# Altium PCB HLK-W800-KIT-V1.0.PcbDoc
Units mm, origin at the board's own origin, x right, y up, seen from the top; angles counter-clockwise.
Board outline 26.04 x 70.01 mm, 2 copper layers (Top Layer, Bottom Layer); 84 components, 58 nets, 293 pads, 279 vias.
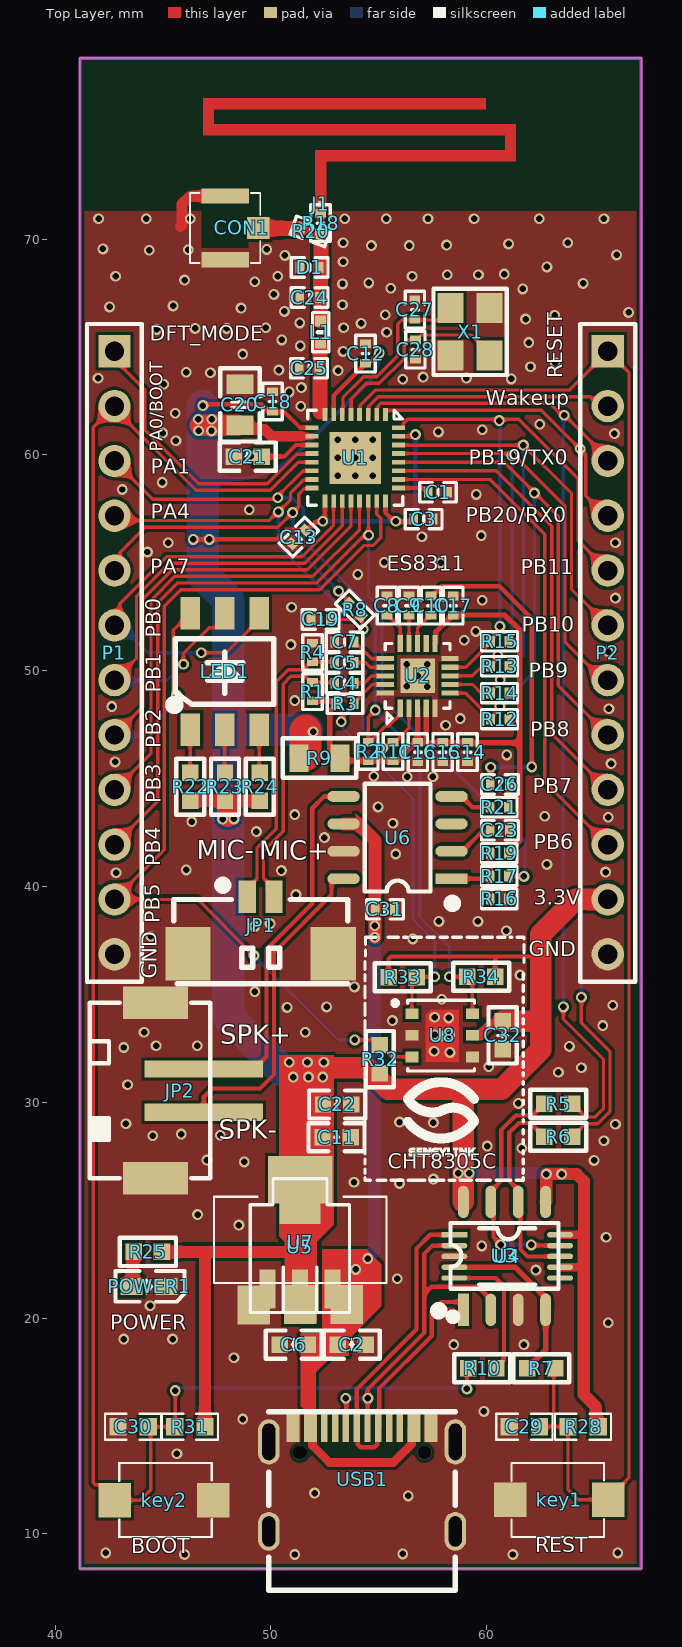
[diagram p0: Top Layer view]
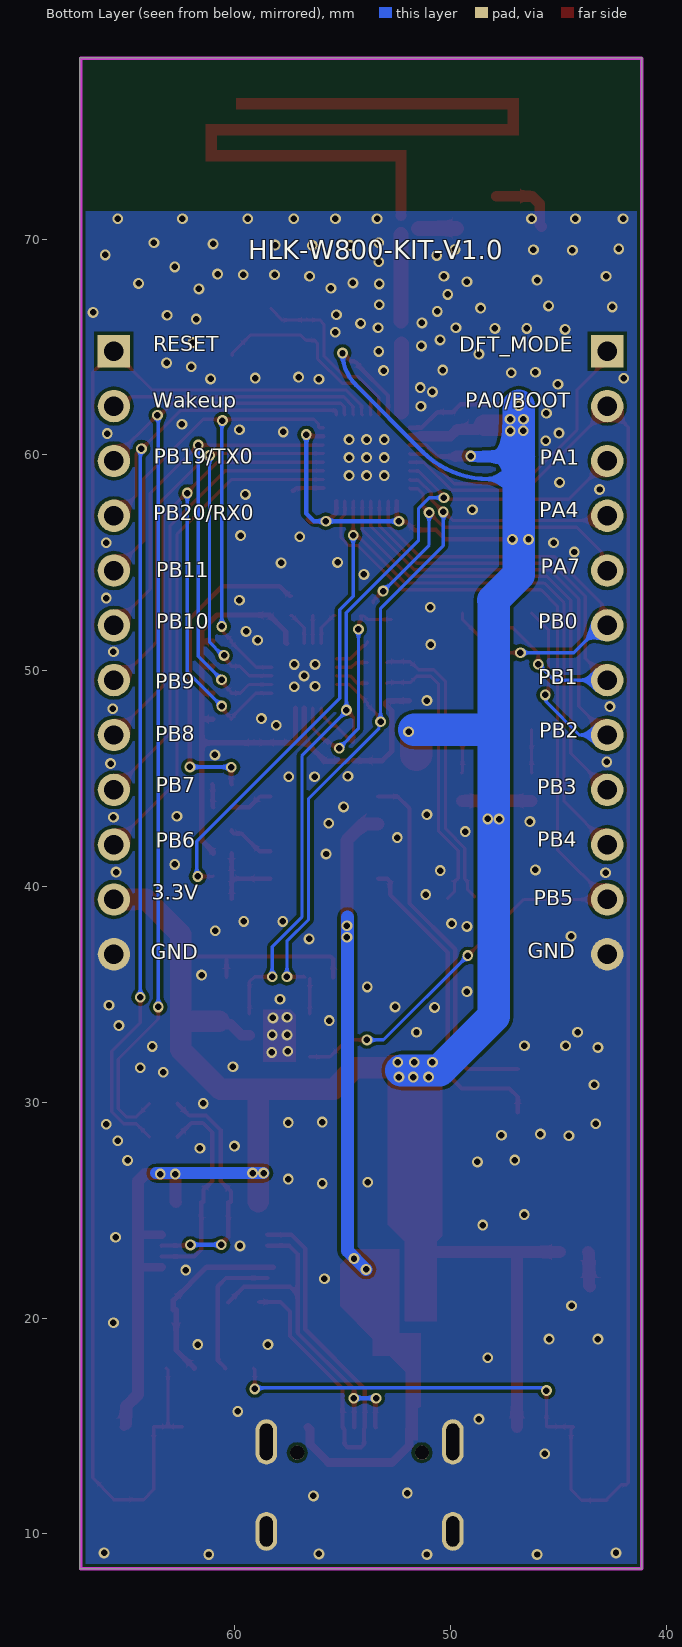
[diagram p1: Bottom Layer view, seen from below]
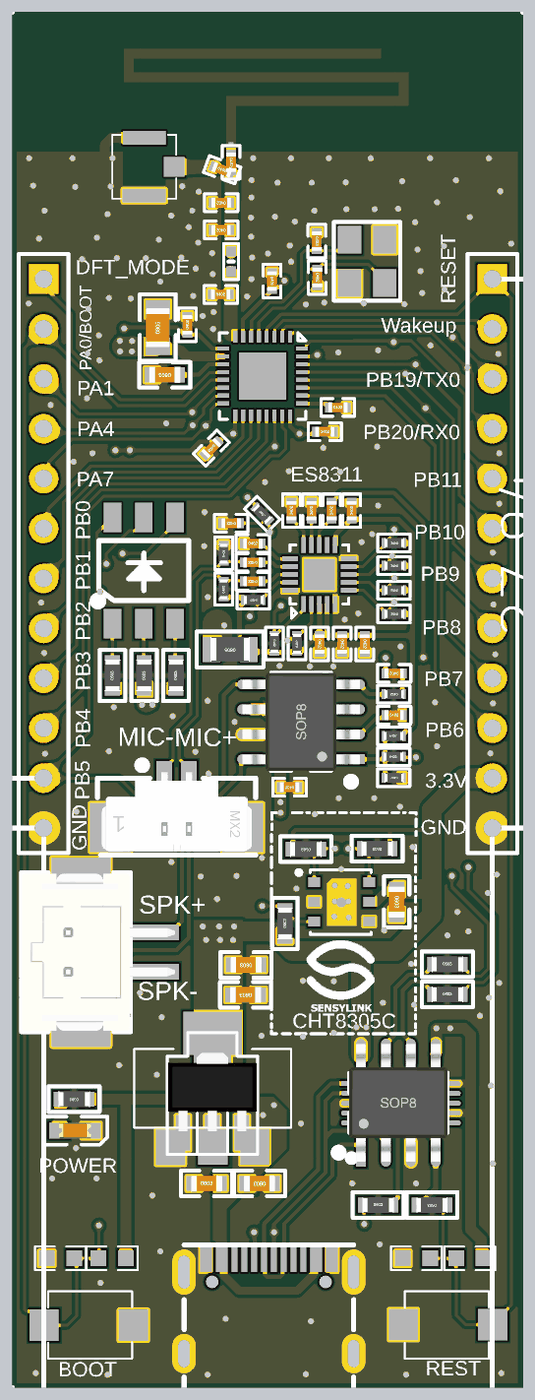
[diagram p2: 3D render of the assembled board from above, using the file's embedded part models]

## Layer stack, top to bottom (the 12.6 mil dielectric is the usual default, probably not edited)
Top Solder: solder mask 0.0102, Solder Resist, Dk 3.5
Top Layer: signal copper 0.0356
Dielectric1: dielectric 0.32, FR-4, Dk 4.8
Bottom Layer: signal copper 0.0356
Bottom Solder: solder mask 0.0102, Solder Resist, Dk 3.5

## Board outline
41.148,8.382 67.183,8.382 67.183,78.382 67.183,78.393 41.148,78.393 41.148,78.382

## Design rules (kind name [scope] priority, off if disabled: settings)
Clearance [All] p1: gap=0.152 ignorepadtopadclearanceinfootprint=FALSE except(0: Arc-Hole Track-Hole SMDPad-Hole THPad-Hole Via-Hole Fill-Hole Poly-Hole Region-Hole Text-Hole)
FabricationTestpoint [(IsPad And (OnTopLayer Or OnBottomLayer))] p1: side=3 testpointundercomponent=TRUE minsize=1.016 maxsize=2.54 preferedsize=1.524 minholesize=0 maxholesize=1.016 preferedholesize=0.813 testpointgrid=0.025 allowsidetop=TRUE allowsidebottom=TRUE usegrid=TRUE gridtolerance=0
PlaneConnect PlaneConnect_1 [InNet('5V')] p1: planeconnectstyle=Direct reliefexpansion=0.508 reliefentries=4 reliefconductorwidth=0.254 reliefairgap=0.254
PlaneConnect [All] p2: planeconnectstyle=Direct reliefexpansion=0.508 reliefentries=4 reliefconductorwidth=0.254 reliefairgap=0.254
PolygonConnect PolygonConnect_1 [InNet('5V')] p1: connectstyle=Direct reliefconductorwidth=0.254 reliefentries=4 polygonreliefangle="90 Angle" airgapwidth=0.254
PolygonConnect [All] p2: connectstyle=Direct reliefconductorwidth=0.254 reliefentries=4 polygonreliefangle="90 Angle" airgapwidth=0.254
RoutingVias [All] p1: holewidth=0.3 width=0.5 viastyle="Through Hole" minholewidth=0.3 minwidth=0.5 maxholewidth=0.5 maxwidth=0.7
SolderMaskExpansion [All] p1: expansion=0.1 istentingtop=FALSE
Width PWER [InNetClass('PWER')] p1: maxlimit=1 minlimit=0.18 preferedwidth=0.75
Width XINHAO [InNetClass('XINHAO')] p2: maxlimit=1 minlimit=0.254 preferedwidth=0.5
Width [All] p3: maxlimit=1.5 minlimit=0.152 preferedwidth=0.254
28 further rules are at their usual default settings.

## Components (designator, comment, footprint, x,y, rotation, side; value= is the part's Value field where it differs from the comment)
C1 "4.7uF" "C 0402_L" 57.742,58.266 r0 top
C2 "100nF" "C 0603_L" 53.746,18.771 r180 top
C3 "100nF" "C 0402_L" 57.074,57.023 r0 top
C4 "1uF" "C 0402_L" 53.409,49.42 r180 top
C5 "1uF" "C 0402_L" 53.409,50.377 r180 top
C6 "10UF" "C 0603_L" 51.054,18.771 r0 top
C7 "1uF" "C 0402_L" 53.409,51.333 r0 top
C8 "1uF" "C 0402_L" 55.372,53.01 r90 top
C9 "1uF" "C 0402_L" 56.396,53.01 r90 top
C10 "100nF" "C 0402_L" 57.421,53.01 r90 top
C11 "100nF" "C 0603_L" 53.037,28.374 r180 top
C12 "10nF" "C 0402_L" 54.381,64.694 r270 top
C13 "100nF" "C 0402_L" 51.292,56.19 r225 top
C14 "10uF" "C 0402_L" 59.106,46.226 r270 top
C15 "100nF" "C 0402_L" 57.956,46.226 r270 top
C16 "100nF" "C 0402_L" 56.806,46.226 r270 top
C17 "10uF" "C 0402_L" 58.445,53.01 r90 top
C18 "10nF" "C 0402_L" 50.072,62.471 r90 top
C19 "39pF" "C 0402_L" 52.306,52.375 r180 top
C20 "47uF" "C 0805_L" 48.565,62.321 r90 top
C21 "10uF" "C 0603_L" 48.92,59.921 r180 top
C22 "10UF" "C 0603_L" 53.061,29.896 r180 top
C23 "1uF" "C 0402_L" 60.604,42.606 r0 top
C24 "1pF" "C 0402_L" 51.791,67.29 r180 top
C25 "BDFN2C051L2" "C 0402_L" 51.765,64.011 r0 top
C26 "100nF" "C 0402_L" 60.604,44.729 r180 top
C27 "15pF" "C 0402_L" 56.667,66.729 r270 top
C28 "15pF" "C 0402_L" 56.693,64.874 r270 top
C29 "100nF" 0603 61.744,14.961 r180 top
C30 "100nF" 0603 43.608,14.961 r180 top
C31 "10uF" "C 0402_L" 55.278,38.938 r180 top
C32 "100nF" "C 0603_L" 60.731,33.096 r270 top value=100pF
CON1 "KH-IPEX-K501-29" SMA/UFLR/NI 47.879,70.513 r90 top
D1 "TPESD3301P" "C 0402_L" 51.795,68.683 r180 top
J1 "" TX1 52.297,71.635 r0 top
JP1 "HDR-1X2" "MX 1.25-LS-2P" 49.534,37.262 r0 top
JP2 "HDR-1X2" PH2.0-LS-2P 44.396,30.54 r90 top
key1 "按键" 正按小龟 65.63,11.586 r180 top
key2 "按键" 正按小龟 42.769,11.556 r0 top
L1 "3nH" 0402A 52.299,65.687 r90 top
LED1 "LED-RGB" "LED 5050" 47.854,49.962 r90 top
P1 "Header 12" HDR1X12 42.748,64.798 r270 top
P2 "Header 12" HDR1X12 65.608,64.798 r270 top
POWER1 "" LED0603 44.348,21.463 r0 top
R1 "2K" "R 0402_L" 51.92,49 r90 top
R2 "2.2K" "R 0402_L" 54.506,46.276 r270 top
R3 "2.2K" "R 0402_L" 53.459,48.463 r180 top
R4 "2K" "R 0402_L" 51.92,50.819 r90 top
R5 "0R" "R 0603_L" 63.315,29.93 r0 top
R6 "0R" "R 0603_L" 63.315,28.397 r0 top
R7 "1K" "R 0603_L" 62.531,17.679 r180 top
R8 "100" "R 0402_L" 53.87,52.851 r315 top
R9 "0R" "R 0805_L" 52.248,45.949 r180 top
R10 "1K" "R 0603_L" 59.792,17.678 r0 top
R11 "1K" "R 0402_L" 55.656,46.226 r90 top
R12 "1K" "R 0402_L" 60.624,47.752 r180 top
R13 "1K" "R 0402_L" 60.624,50.204 r180 top
R14 "1K" "R 0402_L" 60.624,48.96 r180 top
R15 "1K" "R 0402_L" 60.624,51.356 r180 top
R16 "10K" "R 0402_L" 60.604,39.421 r180 top
R17 "1K" "R 0402_L" 60.555,40.483 r0 top
R18 "0R" "C 0402_L" 52.299,70.739 r270 top
R19 "NC/1K" "R 0402_L" 60.555,41.544 r0 top
R20 "NC" "C 0402_L" 51.841,70.358 r340 top
R21 "15K" "R 0402_L" 60.604,43.668 r180 top
R22 "1K" "R 0603_L" 46.253,44.62 r90 top
R23 "1K" "R 0603_L" 47.869,44.62 r90 top
R24 "1K" "R 0603_L" 49.486,44.62 r90 top
R25 "4.7K" "R 0603_L" 44.298,23.063 r180 top
R28 "10K" 0603 64.462,14.961 r0 top
R31 "10K" 0603 46.239,14.961 r0 top
R32 "4.7K" "R 0603_L" 55.042,32.004 r90 top
R33 "4.7K" "R 0603_L" 56.109,35.789 r180 top
R34 "4.7K" "R 0603_L" 59.741,35.814 r180 top
U1 "W800" QFN32_4X4 53.905,59.861 r270 top
U2 "ES8311" ES8311 56.417,50.127 r270 top
U3 "CH340N" SOP8_L 60.822,22.881 r90 top
U4 "CH340E" MSOP10_L 60.949,22.856 r270 top
U5 "AMS1117-3V3" AMS1117 51.463,23.192 r180 top
U6 "ANT8108" SOP8_L 55.865,42.266 r180 top
U7 "AMS1117-3V3" SOT223 50.98,23.624 r90 top
U8 "CHT8305C" "DFN6 3X3" 57.785,33.071 r270 top
USB1 "USB_TYPE_C_16Pin" USB-C-16PIN-1 49.869,14.201 r0 top
X1 "40MHz/10ppm" SMD-3225 59.228,65.7 r90 top

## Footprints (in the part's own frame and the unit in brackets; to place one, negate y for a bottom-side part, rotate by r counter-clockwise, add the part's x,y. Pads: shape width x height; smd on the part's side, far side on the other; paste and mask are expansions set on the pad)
0402A [mil]
  rect 20x20 smd: 1(-20,0) 2(20,0)
  silkscreen extent -36,-15 36,15
0603 [mm]
  rect 0.8x0.8 smd: 1(-0.7,0) 2(0.7,0)
  silkscreen extent -1.3,-0.6 1.3,0.6
AMS1117 [mm] "4.6x4.3x1.6mm(长宽高)"
  rect 0.75x1.8 smd: 1(1.618,1.841) 2(0.118,1.841) 3(-1.382,1.841)
  rect 1.9x1.8 smd: 2(0.118,-2.059)
  silkscreen extent -2.18,-3.26 2.42,2.94, body extent -2.13,-2.23 2.37,1.77, height 1.5
"C 0402_L" [mm] "无极性贴片电容"
  rect 0.4x0.5 smd: 1(-0.45,0) 2(0.45,0)
  silkscreen extent -0.85,-0.45 0.85,0.45, body extent -0.5,-0.26 0.5,0.26, height 0.53
"C 0603_L" [mil] "无极性贴片电容"
  rect 30x30 smd: 1(-25.59,0) 2(25.59,0)
  silkscreen extent -51,-26 51,26, body extent -31,-16 31,16, height 32
"C 0805_L" [mil] "无极性贴片电容"
  rect 35x50 smd: 1(-37.4,0) 2(37.4,0)
  silkscreen extent -67,-36 67,36, body extent -39,-24 39,24, height 20
"DFN6 3X3" [mm]
  rect 0.5x0.6 smd: 1(-1.031,-1.254) 2(-0.031,-1.254) 3(0.969,-1.254) 4(-1.031,1.546) 5(-0.031,1.546) 6(0.969,1.546)
  round 0.5 smd mask+0.051: 7(0,0.127)
  Top Layer region: -1.211,0.913 1.19,0.913 1.19,-0.605 -0.975,-0.605 -1.211,-0.369
  silkscreen extent -1.65,-2.11 1.62,1.65
ES8311 [mm]
  rect 0.8x0.24 smd: 1(1.868,-0.422) 2(1.868,-0.022) 3(1.868,0.378) 4(1.868,0.778) 5(1.868,1.178) 11(-1.132,1.178) 12(-1.132,0.778) 13(-1.132,0.378) 14(-1.132,-0.022) 15(-1.132,-0.422)
  rect 0.24x0.8 smd: 6(1.168,1.878) 7(0.768,1.878) 8(0.368,1.878) 9(-0.032,1.878) 10(-0.432,1.878) 16(-0.432,-1.122) 17(-0.032,-1.122) 18(0.368,-1.122) 19(0.768,-1.122) 20(1.168,-1.122)
  rect 1.6x1.6 smd: 21(0.368,0.378)
  silkscreen extent -1.13,-1.12 2.58,1.88
HDR1X12 [mm] "Connector; Header; 12 Position"
  rect 1.5x1.5 hole 0.9: 1(0,0)
  round 1.5 hole 0.9: 2(2.54,0) 3(5.08,0) 4(7.62,0) 5(10.16,0) 6(12.7,0) 7(15.24,0) 8(17.78,0) 9(20.32,0) 10(22.86,0) 11(25.4,0) 12(27.94,0)
  silkscreen extent -1.27,-1.27 29.21,1.27
LED0603 [mm]
  rect 1x0.8 smd: 1(-0.81,0) 2(0.81,0)
  silkscreen extent -1.55,-0.71 1.65,0.71, body extent -0.81,-0.4 0.81,0.4, height 0.6
"LED 5050" [mm] "白色5050LED"
  rect 1.5x0.9 smd: 1(-2.705,1.6) 2(-2.705,0) 3(-2.705,-1.6) 4(2.705,-1.6) 5(2.705,0) 6(2.705,1.6)
  silkscreen extent -1.52,-2.29 1.52,2.29, body extent -2.7,-2.5 2.7,2.5, height 1.65
MSOP10_L [mm] "塑封体长3mm，宽3mm，脚距0.5"
  rect 0.25x1.2 smd: 1(-1,-2.45)
  oval 0.25x1.2 smd: 2(-0.5,-2.45) 3(0,-2.45) 4(0.5,-2.45) 5(1,-2.45) 6(1,2.45) 7(0.5,2.45) 8(0,2.45) 9(-0.5,2.45) 10(-1,2.45)
  silkscreen extent -1.3,-2.67 2.95,1.3, body extent -1.5,-2.45 1.5,2.45, height 0.95
"MX 1.25-LS-2P" [mm] "长：7.25m，宽：3.7mm，高：4.7mm"
  rect 2.1x2.5 smd: 0(-3.382,-0.381) 0(3.354,-0.381)
  rect 0.8x1.5 smd: 1(-0.639,2.261) 2(0.611,2.261)
  silkscreen extent -4.04,-1.78 4.02,2.99, body extent -3.83,-1.6 3.83,2.5, height 4.7
PH2.0-LS-2P [mm] "长：8mm，宽：5.5mm，高：6.1mm"
  rect 1.5x3 smd: 0(-4.064,-0.254) 0(4.064,-0.254)
  rect 0.8x5.5 smd: 1(-1,-2.492) 2(1,-2.492)
  silkscreen extent -4.06,-2.79 4.06,2.79, body extent -4,-5.05 4,2.75, height 6.15
QFN32_4X4 [mm]
  rect 0.6x0.22 smd: 1(-2,1.4) 2(-2,1) 3(-2,0.6) 4(-2,0.2) 5(-2,-0.2) 6(-2,-0.6) 7(-2,-1) 8(-2,-1.4) 17(2,-1.4) 18(2,-1) 19(2,-0.6) 20(2,-0.2) 21(2,0.2) 22(2,0.6) 23(2,1) 24(2,1.4)
  rect 0.22x0.6 smd: 9(-1.4,-2) 10(-1,-2) 11(-0.6,-2) 12(-0.2,-2) 13(0.2,-2) 14(0.6,-2) 15(1,-2) 16(1.4,-2) 25(1.4,2) 26(1,2) 27(0.6,2) 28(0.2,2) 29(-0.2,2) 30(-0.6,2) 31(-1,2) 32(-1.4,2)
  rect 2.4x2.4 smd: 33(0,0)
  silkscreen extent -2.2,-2.2 2.2,2.2
"R 0402_L" [mm] "1/16W贴片电阻"
  rect 0.4x0.5 smd: 1(-0.4,0) 2(0.45,0)
  silkscreen extent -0.8,-0.45 0.85,0.45, body extent -0.5,-0.25 0.5,0.25, height 0.3
"R 0603_L" [mil] "1/10W贴片电阻"
  rect 30x30 smd: 1(-25.59,0) 2(25.59,0)
  silkscreen extent -51,-26 51,26, body extent -31,-16 32,16, height 16
"R 0805_L" [mil] "1/8W贴片电阻"
  rect 35x50 smd: 1(-37.4,0) 2(37.4,0)
  silkscreen extent -67,-36 67,36, body extent -39,-25 39,25, height 20
SMA/UFLR/NI [mm] "一代天线座子"
  rect 1x1.05 smd: 1(0,-1.525)
  rect 0.7x2.2 smd: 2(-1.472,0.006) 3(1.475,0)
  Top Layer pour cut-out: -0.95,1.1 0.95,1.1 0.95,-1.1 0.5,-1.1 0.5,-1 -0.5,-1 -0.5,-1.1 -0.95,-1.1 -0.95,1.1
  silkscreen extent -1.63,-1.63 1.63,1.63
SMD-3225 [mm]
  rect 1.4x1.2 smd: 1(-1.1,-0.9) 2(1.1,-0.9) 3(1.1,0.9) 4(-1.1,0.9)
  silkscreen extent -2,-1.7 2,1.7
SOP8_L [mm] "5*6*1.8mm（长宽高）"
  rect 1.5x0.5 smd: 1(-2.5,1.905)
  oval 1.5x0.5 smd: 2(-2.5,0.635) 3(-2.5,-0.635) 4(-2.5,-1.905) 5(2.5,-1.905) 6(2.5,-0.635) 7(2.5,0.635) 8(2.5,1.905)
  silkscreen extent -2.69,-2.5 1.52,3.2, body extent -3,-2.5 3,2.5, height 1.9
SOT223 [mm] "6.4x7x1.6mm(长宽高)"
  rect 1.8x1.5 smd: 1(-3.017,1.772) 2(-2.995,-0.384) 3(-2.995,-2.534)
  rect 2.2x3 smd: 2(2.794,-0.381)
  silkscreen extent -2.01,-4.38 1.99,3.62
TX1 [mil]
  rect 10x10 smd mask+3.94: 1(0,0)
  Top Layer region: 301.34,192.19 -214.41,192.19 -214.41,125.26 336.77,125.26 336.77,97.7 -9.68,97.7 -9.68,-15 10,-15 10,78.02 356.46,78.02 356.46,144.94 -194.72,144.94 -194.72,172.5 301.34,172.5
USB-C-16PIN-1 [mm]
  oval 1x2.099 hole 0.6 slot 1.7 at 90 deg: 1(0.034,0.061) 2(8.674,0.061)
  oval 1x1.799 hole 0.6 slot 1.4 at 90 deg: 3(0.034,-4.088) 4(8.674,-4.088)
  rect 0.6x1.35 smd: A1B12(1.154,0.736) A4B9(1.954,0.736) B1A12(7.554,0.736) B4A9(6.754,0.736)
  rect 0.3x1.35 smd: A5(3.104,0.736) A6(4.104,0.736) A7(4.604,0.736) A8(2.604,0.736) B5(6.104,0.736) B6(5.104,0.736) B7(3.604,0.736) B8(5.604,0.736)
  round 0.65 hole 0.65 unplated: ""(1.464,-0.438) ""(7.244,-0.438)
  silkscreen extent 0.04,-6.81 8.67,1.45
正按小龟 [mm]
  rect 1.5x1.6 smd: 1(0,0) 2(4.55,0)
  silkscreen extent 0.2,-1.7 4.48,1.73

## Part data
C1 C3 C4 C5 C7 C8 C9 C10 C12 C13 C14 C15 C16 C17 C18 C19 C20 C21 C23 C24 C26 C31 R18 R20: library part "CAP NP_Dup2"
C2 C6 C11 C22: library part C, "无极性贴片电容"
C25: library part "CAP NP"
C27 C28 C29 C30: library part "CAP NP_Dup1"
C32: library part Cap, "Capacitor"
CON1: BOM_Manufacturer="Shenzhen Kinghelm Elec"
D1: library part PT05D5CE, BOM_Manufacturer="PTTC(Polytronics Tech)"
J1: library part Component_1
JP1 JP2: library part "Header 2", "2P接插件"
L1: library part INDUCTOR
LED1: "三基色LED"
P1 P2: "Header, 12-Pin"
POWER1: library part LED
R1 R4: library part R_Dup1
R2 R3 R9 R16 R21: library part RES
R5 R6 R7 R10 R22 R23 R24 R25 R28 R31 R32 R33 R34: library part Res1, "Resistor"
R8: library part RES1, "R?"
R11 R12 R13 R14 R15 R17 R19: library part R
U1: library part W600_10
U2: library part ES8374_0
U3: BOM_JLCPCB Part Class="Extended Part", BOM_Manufacturer="WCH(Jiangsu Qin Heng)"
U5 U7: library part AMS1117, "三端稳压芯片"
U6: library part W25Q16_5
U8: "温度传感器"
X1: library part OSC44M_5

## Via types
v1: diameter 0.5, hole 0.3, Top Layer to Bottom Layer, tented both sides, 279 vias

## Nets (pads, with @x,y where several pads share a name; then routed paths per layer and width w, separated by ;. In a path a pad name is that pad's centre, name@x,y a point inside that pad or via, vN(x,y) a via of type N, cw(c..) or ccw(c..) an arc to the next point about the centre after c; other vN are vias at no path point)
5V: C2.2 C6.2 C31.2 U5.3 U6.6 U7.3 USB1.A4B9 USB1.B4A9 | length 29.9
  Top Layer w0.4: USB1.A4B9 51.923,14.838 51.923,14.096 52.714,13.305 55.665,13.305 56.523,14.164 56.523,14.838 USB1.B4A9
  Top Layer w0.6: U6.6 54.051,42.901 54.813,42.139 v1(54.813,38.176) v1(54.813,37.643)
  Bottom Layer w0.6: v1(53.924,22.25) 54.788,23.114 54.788,38.583
  other v1: 54.483,22.758
ANT: C25.2 L1.1 U1.8 | length 3.2
  Top Layer w0.7: C25.2@52.273,64.011 L1.1@52.273,65.128 ; 52.277,61.979 C25.2@52.277,64.04
CH_DM: U3.2 U4.2 USB1.A7 USB1.B7 | length 16.7
  Top Layer w0.2: v1(53.463,16.286) 53.493,16.256 53.493,14.957 USB1.B7 ; USB1.A7 54.473,16.286 54.473,16.688 57.097,19.312 57.097,21.101 ; U4.2 57.489,23.356 57.097,22.964 57.097,21.101 ; U3.2@60.314,20.719 59.583,21.45 57.446,21.45 57.097,21.101
  Bottom Layer w0.2: v1(53.463,16.286) v1(54.493,16.286) v1@54.498,16.281
CH_DP: U3.1 U4.1 USB1.A6 USB1.B6 | length 22.1
  Top Layer w0.2: USB1.B6 55.013,14.977 55.013,16.729 57.449,19.166 57.449,20.303 57.894,20.748 U3.1@58.872,20.748 ; USB1.B6@54.998,14.913 54.923,14.838 54.923,14.144 54.79,14.01 54.157,14.01 54.023,14.144 54.023,14.888 USB1.A6 53.981,14.945 53.981,16.715 56.745,19.479 56.745,23.222 57.379,23.856 U4.1
DAC_OUT: C10.2 C26.2 | length 15.1
  Top Layer w0.2: C10.2 57.471,53.46 57.923,53.912 60.593,53.912 62.088,52.417 v1(62.088,45.537) ; C26.2 60.142,44.742 60.176,44.777 60.176,45.52 v1(60.174,45.522)
  Bottom Layer w0.2: v1(60.174,45.522) 60.188,45.537 v1(62.088,45.537)
DFT_MODE: P1.1 U1.12 | length 13.6
  Top Layer w0.152: P1.1@42.494,64.672 44.145,63.021 44.145,61.172 46.652,58.665 49.836,58.665 51.205,60.034 51.675,60.034 51.878,60.034 U1.12
GND: C1.2 C2.1 C3.2 C6.1 C7.1 C8.2 C9.2 C11.1 C12.1 C13.2 C14.2 C15.2 C16.2 C17.2 C18.2 C19.2 C20.2 C21.2 C22.1 C23.2 C24.2 C25.1 C27.1 C28.2 C29.2 C30.2 C31.1 C32.2 CON1.2 CON1.3 D1.2 JP1.0 JP2.0 key1.2 key2.2 P1.12 P2.12 POWER1.2 R4.2 R16.1 U1.33 U2.5 U2.10 U2.20 U2.21 U3.3 U4.3 U5.1 U6.7 U7.1 U8.2 U8.6 U8.7 USB1.1 USB1.2 USB1.3 USB1.4 USB1.A1B12 USB1.B1A12 X1.2 X1.4 | length 3.2
  Top Layer w0.5: 45.796,70.587 45.872,70.663 45.872,71.628 46.233,71.988 CON1.3
  other v1: 45.999,9.042 51.105,9.042 61.214,9.042 56.109,9.068 42.342,9.119 66.065,9.119 56.363,11.76 52.019,11.887 45.644,13.716 48.692,15.316 59.868,15.672 48.285,18.161 58.471,18.771 61.722,18.771 43.18,19.025 45.441,19.025 65.634,19.787 44.399,20.574 55.855,21.819 62.281,22.225 59.766,23.343 65.532,23.749 48.514,24.308 46.598,24.792 55.956,26.238 53.848,26.289 57.531,26.441 48.763,27.237 47.034,27.317 64.973,27.305 61.62,27.864 60.025,27.971 65.43,28.219 44.526,28.448 47.65,28.473 45.847,28.524 65.962,28.981 43.282,29.007 57.531,29.058 55.956,29.083 61.468,29.947 43.358,30.81 63.322,31.394 64.389,31.598 60.096,31.648 58.293,32.309 57.556,32.36 43.18,32.537 63.83,32.588 44.679,32.614 46.584,32.614 57.582,33.122 58.268,33.122 44.12,33.249 51.587,33.249 65.38,33.553 55.626,33.782 58.242,33.909 57.582,33.934 50.749,34.392 52.578,34.417 65.837,34.493 57.912,34.773 49.251,35.128 53.869,35.342 61.544,35.89 56.566,37.567 44.425,37.694 60.909,37.948 49.251,38.151 49.962,38.278 57.785,38.379 59.588,38.379 51.156,39.624 42.824,40.64 65.507,40.665 50.486,40.739 46.076,40.767 62.789,41.021 55.778,41.504 52.476,42.266 49.327,42.545 55.651,42.926 46.331,43.007 65.634,43.205 62.687,43.256 51.105,43.332 54.966,43.688 56.312,45.085 57.506,45.085 54.762,45.11 65.761,45.695 42.774,45.771 60.928,46.095 58.09,47.473 58.776,47.777 65.659,48.235 42.621,48.336 51.105,48.616 57.252,49.251 56.286,49.276 56.794,49.759 56.286,50.292 57.252,50.292 65.634,50.876 50.927,51.206 58.953,51.41 59.487,51.816 50.952,52.934 59.792,53.264 65.964,53.365 54.026,54.458 57.861,54.991 55.245,55.016 44.272,55.499 45.237,55.931 65.964,55.931 56.998,56.21 59.741,56.261 48.995,57.452 59.512,58.166 43.104,58.395 44.958,58.725 53.086,59.042 53.899,59.042 54.712,59.042 53.086,59.875 53.899,59.875 54.712,59.875 45.593,60.655 53.086,60.709 53.899,60.709 54.712,60.709 65.913,60.985 44.983,61.011 57.76,61.062 59.792,61.166 62.459,61.417 45.568,61.925 51.384,62.255 50.851,62.916 51.41,63.119 45.034,63.271 56.109,63.5 61.13,63.52 41.986,63.551 59.056,63.557 57.048,63.602 47.193,63.805 46.076,63.83 53.111,63.906 50.368,63.932 62.027,64.084 63.17,64.262 48.692,64.668 53.34,64.795 51.359,65.049 61.951,65.202 50.495,65.329 55.356,65.679 44.704,65.811 46.482,65.862 47.955,65.862 49.759,65.888 53.365,65.888 54.178,66.091 51.333,66.116 61.798,66.294 63.144,66.472 55.296,66.497 66.573,66.599 50.622,66.65 48.616,66.802 42.52,66.853 45.466,66.904 53.315,66.954 50.14,67.437 61.671,67.691 55.55,67.716 53.315,67.92 64.465,67.945 54.534,67.97 49.251,68.021 45.999,68.097 42.799,68.275 50.317,68.275 56.54,68.275 58.166,68.351 59.614,68.351 60.808,68.377 62.789,68.707 53.34,68.947 50.648,69.243 66.015,69.266 44.361,69.483 46.169,69.505 49.809,69.52 42.215,69.545 54.658,69.7 56.409,69.7 58.141,69.723 61.011,69.774 53.34,69.832 63.754,69.825 42.012,70.942 44.221,70.942 46.256,70.942 53.416,70.942 55.347,70.942 57.277,70.942 59.411,70.942 62.433,70.942 65.43,70.942
MIC+: C4.2 JP1.2 R1.2 | length 13.2
  Top Layer w0.152: JP1.2@50.145,39.446 49.821,39.77 49.821,40.221 49.656,40.387 49.656,41.652 50.565,42.56 50.565,49.379 50.923,49.737 51.584,49.737 51.87,49.45 52.929,49.45 C4.2
MIC-: C5.2 JP1.1 R4.1 | length 13.6
  Top Layer w0.152: JP1.1 49.219,39.846 49.219,40.218 49.351,40.35 49.351,41.778 50.24,42.666 50.24,49.485 50.796,50.042 51.493,50.042 51.87,50.419 R4.1 52.917,50.419 C5.2
NetC1_1: C1.1 U1.25 | length 1.5
  Top Layer w0.2: U1.25 57.156,58.461 57.278,58.339 C1.1@57.328,58.339
NetC4_1: C4.1 U2.18 | length 1.6
  Top Layer w0.152: C4.1 54.329,49.42 54.666,49.756 55.292,49.756 U2.18
NetC5_1: C5.1 U2.17 | length 1.5
  Top Layer w0.152: C5.1 54.39,50.377 54.608,50.159 U2.17
NetC7_2: C7.2 U2.16 | length 1.8
  Top Layer w0.152: C7.2 53.859,51.283 53.983,51.16 54.065,51.16 54.666,50.559 U2.16
NetC8_1: C8.1 U2.15 | length 1.6
  Top Layer w0.152: C8.1 55.422,52.56 55.994,51.987 U2.15
NetC9_1: C9.1 U2.14 | length 1.3
  Top Layer w0.152: U2.14 56.394,52.558 C9.1
NetC10_1: C10.1 U2.13 | length 1.6
  Top Layer w0.152: U2.13 56.794,51.983 57.371,52.56 C10.1
NetC23_1: C23.1 U6.2 | length 2.2
  Top Layer w0.2: U6.2 58.865,41.631 59.691,42.456 60.054,42.456 60.154,42.556 C23.1
NetC24_1: C24.1 D1.1 L1.2 R18.2 R20.2 | length 4
  Top Layer w0.7: L1.2 52.299,67.313 D1.1@52.299,68.766 ; D1.1@52.313,68.806 R20.2@52.313,70.209
NetC26_1: C26.1 R21.1 | length 1.1
  Top Layer w0.2: R21.1 61.029,43.693 61.029,44.704 C26.1
NetCON1_1: CON1.1 R20.1 | length 1.8
  Top Layer w0.7: CON1.1@49.727,70.494 R20.1@51.486,70.494
NetJ1_1: J1.1 R18.1 | length 0
  Top Layer w0.5: R18.1@52.299,71.082 52.299,71.106 R18.1@52.302,71.11
NetLED1_1: LED1.1 R22.2 | length 2
  Top Layer w0.152: R22.2 LED1.1
NetLED1_2: LED1.2 R23.2 | length 2
  Top Layer w0.152: LED1.2 47.854,45.285 R23.2
NetLED1_3: LED1.3 R24.2 | length 2
  Top Layer w0.152: LED1.3 49.454,45.302 R24.2
NetPOWER1_1: POWER1.1 R25.2 | length 1.6
  Top Layer w0.56: POWER1.1 43.593,21.518 43.593,23.009 R25.2
NetR10_2: R10.2 U4.5 | length 6.4
  Top Layer w0.2: U4.5 60.415,21.856 60.8,21.47 60.8,18.037 R10.2
NetR16_2: R16.2 R17.1 R19.1 U6.1 | length 4
  Top Layer w0.2: U6.1 60.054,40.361 R17.1@60.154,40.461 ; R16.2 R17.1@60.154,40.461 ; R19.1 R17.1 R17.1@60.154,40.461
NetR21_2: R21.2 U6.4 | length 2
  Top Layer w0.2: U6.4 58.835,44.171 59.338,43.668 R21.2
PA0/BOOT: C30.1 key2.1 P1.2 R10.1 R31.1 U1.13 | length 85.4
  Top Layer w0.152: v1(45.568,16.637) 45.568,14.99 R31.1 C30.1 44.425,14.845 44.425,12.04 43.941,11.556 key2.1 42.769,11.606 42.095,12.28 41.859,12.28 41.77,12.369 41.77,61.28 P1.2 42.748,62.138 46.526,58.36 49.962,58.36 51.263,59.661 51.326,59.661 U1.13 ; v1(59.08,16.713) 59.08,17.617 R10.1
  Bottom Layer w0.152: v1(45.568,16.637) 45.662,16.637 45.789,16.765 59.029,16.765 v1(59.08,16.713)
PA1: P1.3 R2.1 R34.2 U1.14 U2.1 U8.4 | length 43
  Top Layer w0.152: P1.3 44.529,57.937 50.054,57.937 50.064,57.947 50.251,57.947 v1(50.317,58.014) 50.317,58.093 51.472,59.248 51.892,59.248 51.895,59.251 U1.14 ; v1(54.837,48.172) 54.506,47.841 R2.1 54.556,46.676 55.33,47.449 55.465,47.449 55.994,47.979 U2.1 ; v1(58.268,35.814) R34.2 59.331,35.574 U8.4
  Bottom Layer w0.152: v1(50.317,58.014) 50.994,58.014 51.489,57.518 51.489,56.039 54.837,52.692 v1(54.837,48.172) 54.837,48.11 56.896,46.05 56.896,38.583 58.276,37.202 v1@58.276,35.814 ; v1(58.268,35.814) v1@58.276,35.814
PA4: P1.4 R3.1 R33.1 U1.15 U2.19 U8.1 | length 40.2
  Top Layer w0.152: P1.4 42.967,56.959 49.916,56.959 50.31,57.353 v1(50.343,57.353) 50.343,57.362 50.907,57.927 50.907,58.235 51.5,58.827 51.872,58.827 U1.15 ; v1(53.254,47.634) 53.321,47.701 53.321,47.875 53.859,48.413 R3.1 53.859,48.513 54.704,49.359 U2.19 ; U8.1 56.531,35.728 R33.1@56.54,35.738 ; R33.1 56.809,35.839 56.835,35.814 v1(57.591,35.814)
  Bottom Layer w0.152: v1(50.343,57.353) 50.343,55.795 53.254,52.884 v1(53.254,47.634) 53.321,47.568 53.321,47.339 56.591,44.069 56.591,38.456 57.591,37.456 v1(57.591,35.814)
PA7: P1.5 R8.1 U1.16 | length 16.4
  Top Layer w0.152: P1.5@43.006,54.896 43.006,55.48 44.17,56.644 50.321,56.644 v1@51.045,57.369 ; v1(51.003,57.328) 51.282,57.607 51.282,58.178 51.531,58.427 51.872,58.427 U1.16 ; v1(53.134,53.689) 53.587,53.236 R8.1
  Bottom Layer w0.152: v1(51.003,57.328) 51.003,55.821 v1@53.134,53.69
PA7/I2S_MCK: C19.1 R8.2 R11.2 U2.2 | length 10.6
  Top Layer w0.152: C19.1 53.857,52.375 54.015,52.533 R8.2 54.153,52.498 54.153,52.323 54.268,52.208 v1@54.268,52.135 ; v1(55.169,46.406) 55.218,46.406 55.227,46.397 55.233,46.404 55.334,46.404 55.606,46.676 R11.2 ; R11.2@55.631,46.701 55.705,46.775 R11.2@55.83,46.775 ; R11.2@55.701,46.63 56.394,47.324 U2.2
  Bottom Layer w0.152: v1(54.275,51.923) 54.275,47.299 v1(55.169,46.406)
PB0: LED1.4 P1.6 U1.18 | length 21.8
  Top Layer w0.152: P1.6 42.992,52.342 42.992,53.105 45.17,55.283 51.439,55.283 52.901,56.746 52.901,57.857 U1.18 ; v1(46.771,50.83) 47.917,50.83 49.454,52.367 LED1.4
  Bottom Layer w0.152: P1.6 43.033,52.098 44.301,50.83 v1(46.771,50.83)
PB1: LED1.5 P1.7 U1.19 | length 23.1
  Top Layer w0.152: P1.7 43.768,50.578 43.768,53.45 45.296,54.978 51.565,54.978 53.305,56.719 U1.19 ; v1(45.947,50.301) 45.947,50.808 47.132,51.993 47.48,51.993 47.854,52.367 LED1.5@47.854,52.559
  Bottom Layer w0.152: P1.7 45.204,49.558 v1(45.947,50.301)
PB2: LED1.6 P1.8 U1.20 | length 27
  Top Layer w0.152: P1.8 44.073,48.343 44.073,53.324 45.422,54.673 51.691,54.673 53.705,56.688 U1.20 ; v1(45.623,48.879) 45.468,49.033 45.468,51.882 LED1.6
  Bottom Layer w0.152: P1.8 44.046,47.018 45.578,48.551 45.578,48.834 v1(45.623,48.879)
PB3: P1.9 U1.21 | length 21.8
  Top Layer w0.152: P1.9 44.444,46.174 44.444,53.264 45.549,54.369 51.946,54.369 54.105,56.528 U1.21
PB4: P1.10 R17.2 U1.22 | length 44.3
  Top Layer w0.152: P1.10 44.749,43.939 44.749,53.138 45.675,54.064 52.122,54.064 54.333,56.275 v1(54.522,56.275) 54.522,57.837 54.502,57.858 U1.22 ; R17.2 61.025,40.462 v1(61.722,40.462)
  Bottom Layer w0.152: v1(54.522,56.275) 54.522,53.438 55.141,52.818 55.141,48.719 61.773,42.088 61.773,40.513 v1(61.722,40.462)
PB5: P1.11 R32.2 U1.23 U8.3 | length 44.5
  Top Layer w0.152: v1(49.21,36.796) 46.608,39.398 P1.11 45.054,41.704 45.054,52.991 45.816,53.753 52.254,53.753 54.298,55.797 54.72,55.797 55.084,56.161 55.084,57.067 54.905,57.245 U1.23 ; v1(53.882,32.89) 54.805,32.89 55.594,32.102 U8.3
  Bottom Layer w0.152: v1(49.21,36.796) 53.116,32.89 v1(53.882,32.89)
PB6/TX1: P2.10 U1.26 | length 23.4
  Top Layer w0.152: U1.26 60.143,58.861 62.69,56.313 62.69,44.856 P2.10
PB7/RX1: P2.9 U1.27 | length 21.5
  Top Layer w0.152: U1.27 59.208,59.261 60.449,59.261 63.012,56.698 63.012,47.075 P2.9
PB8: P2.8 R12.2 U1.28 U2.6 | length 33.2
  Top Layer w0.152: U1.28 59.238,59.661 60.811,59.661 63.317,57.156 63.317,49.31 P2.8 ; U2.6 59.033,48.959 60.05,47.942 60.05,47.876 R12.2 ; R12.2@60.174,47.802 60.542,48.171 60.542,48.29 v1(60.608,48.356)
  Bottom Layer w0.152: v1(60.608,48.356) 62.209,49.957 v1(62.209,58.227)
PB9: P2.7 R13.2 U1.29 U2.8 | length 30
  Top Layer w0.152: U1.29 55.911,60.066 59.264,60.066 v1@61.176,60.066 ; U2.8 59.334,49.759 59.78,50.204 R13.2 60.174,50.254 60.505,50.585 v1(60.505,50.704) ; v1@61.233,60.03 63.621,57.641 63.621,51.336 63.866,51.091 65.399,49.558 P2.7
  Bottom Layer w0.152: v1(60.505,50.704) 60.574,50.704 60.636,50.766 61.176,51.306 v1(61.176,59.973)
PB10: P2.6 R14.2 U1.30 U2.7 | length 29.9
  Top Layer w0.152: U1.30 55.915,60.451 v1(61.7,60.451) 63.926,58.225 63.926,53.78 P2.6 ; U2.7 59.352,49.359 59.751,48.96 R14.2 ; R14.2@60.174,49.01 60.555,49.391 60.555,49.515 v1(60.621,49.582)
  Bottom Layer w0.152: v1(60.621,49.582) 61.7,50.661 v1(61.7,60.451)
PB11: P2.5 R15.2 U1.32 U2.9 | length 27.4
  Top Layer w0.152: U1.32 56.095,61.261 56.129,61.295 56.129,61.441 56.337,61.649 58.511,61.649 60.579,61.649 61.477,61.649 64.231,58.895 64.231,56.015 P2.5 ; U2.9 59.019,50.159 60.043,51.183 60.05,51.183 60.174,51.307 60.174,51.407 60.297,51.53 60.542,51.774 60.542,51.985 v1(60.608,52.052)
  Bottom Layer w0.152: v1(60.579,61.59) 60.608,61.561 v1(60.608,52.052)
PB19/TX0: P2.3 R5.2 U1.2 | length 47.1
  Top Layer w0.152: U1.2 54.939,61.895 54.939,62.238 55.091,62.39 58.071,62.39 58.076,62.385 62.916,62.385 63.469,61.833 v1(63.59,61.833) 63.609,61.833 65.608,59.833 P2.3 ; v1(63.551,34.417) 63.551,33.858 65.405,32.004 65.405,29.692 65.033,29.32 64.574,29.32 R5.2
  Bottom Layer w0.152: v1(63.551,34.417) 63.551,61.793 v1(63.59,61.833)
PB20/RX0: P2.4 R6.2 U1.1 | length 47.2
  Top Layer w0.152: U1.1 55.305,62.035 55.339,62.069 59.65,62.069 62.52,62.069 64.588,60.001 64.588,58.097 65.507,57.178 P2.4 ; R6.2 64.574,29.007 65.151,29.007 65.71,29.566 65.71,32.359 64.918,33.15 64.385,33.684 v1(64.385,34.868)
  Bottom Layer w0.152: v1(64.336,60.287) 64.385,60.238 v1(64.385,34.868)
RESET: C29.1 key1.1 P2.1 R7.1 R28.1 U1.4 | length 76
  Top Layer w0.152: U1.4 54.139,61.895 54.139,62.3 54.841,63.002 63.821,63.002 64.934,64.115 64.934,64.124 P2.1 66.587,63.82 66.587,12.593 65.63,11.636 key1.1 64.233,11.586 63.762,12.057 R28.1 63.103,14.961 ; C29.1 63.103,14.961 ; R7.1 63.103,17.601 63.103,14.961
RTS: R7.2 U3.4 U4.4 | length 8.8
  Top Layer w0.254: U4.4@58.219,22.356 U4.4 61.318,22.356 62.854,20.82 U3.4@62.854,20.381 ; R7.2 62.727,18.525 U3.4
RXD: R5.1 U3.7 U4.9 | length 10.9
  Top Layer w0.2: U3.7 60.187,25.87 60.665,26.348 60.665,28.712 61.341,29.388 62.122,29.388 R5.1 ; U3.7@60.314,25.381 60.314,23.749 60.639,23.425 v1(60.639,23.399) ; v1(62.066,23.389) 62.09,23.365 63.389,23.365 U4.9
  Bottom Layer w0.2: v1(60.639,23.399) 62.057,23.399 v1(62.066,23.389)
SP+: JP2.2 U6.5 | length 17.2
  Top Layer w0.2: JP2.2 49.238,31.54 49.538,31.84 49.538,31.86 49.789,32.111 49.789,37.091 51.912,39.214 51.912,43.621 52.462,44.171 U6.5
SP-: JP2.1 U6.8 | length 15
  Top Layer w0.2: JP2.1 46.888,30.24 47.286,30.638 49.493,30.638 50.141,31.286 50.141,36.945 52.808,39.611 52.808,40.222 52.947,40.361 U6.8
TXD: R6.1 U3.6 U4.8 | length 9.6
  Top Layer w0.2: U3.6 61.457,25.94 61.045,26.352 61.045,28.593 61.487,29.035 62.026,29.035 62.383,28.678 R6.1 ; U3.6@61.564,25.381 61.564,23.181 61.889,22.856 U4.8
V33: C14.1 C15.1 C16.1 C17.1 R1.1 R2.2 R3.2 R9.1 R11.1 R12.1 R13.1 R14.1 R15.1 R19.2 U2.3 U2.4 U2.11 | length 33.5
  Top Layer w0.25: R1.1 52.922,48.6 53.009,48.513 R3.2 53.009,48.413 52.727,48.131 52.727,46.28 53.181,45.826 R2.2 ; 54.762,45.81 R11.1@55.78,45.81 ; R11.1@55.83,45.81 56.606,46.585 56.724,46.585 C16.1@56.799,46.66 ; U2.3 56.797,48.256 56.797,46.662 C16.1@56.799,46.66 ; U2.4 57.194,46.773 57.308,46.66 ; U2.11 57.638,51.302 57.638,51.803 58.395,52.56 C17.1 58.465,52.579 60.827,52.579 61.532,51.874 61.532,51.333 ; C14.1@59.106,46.66 57.956,46.66 57.308,46.66 ; C14.1 59.129,46.652 61.532,46.652 ; R19.2 61.004,41.594 61.532,42.122 61.532,46.652 ; R12.1 61.507,47.752 61.532,47.777 ; R14.1 61.467,48.96 61.532,48.895 ; R13.1 61.518,50.204 61.532,50.19 ; R15.1 61.509,51.357 61.532,51.333 ; C16.1@56.799,46.66 57.194,46.66 57.308,46.66 ; 61.532,46.652 61.532,47.777 ; 61.532,47.777 61.532,48.895 ; 61.532,48.895 61.532,50.19 ; 61.532,50.19 61.532,51.333
VCC_33: C3.1 C11.2 C12.2 C13.1 C18.1 C20.1 C21.1 C22.2 C32.1 P2.11 R9.2 R22.1 R23.1 R24.1 R25.1 R28.2 R31.2 R32.1 R33.2 R34.1 U1.7 U1.9 U1.10 U1.11 U1.17 U1.24 U1.31 U3.5 U3.8 U4.7 U4.10 U5.2 U7.2 U8.5 | length 166.8
  Top Layer w0.2: v1(46.397,56.083) v1(47.142,56.083) 50.245,56.083 50.685,56.523 51.412,56.523 51.433,56.544 51.469,56.508 C13.1 51.67,56.508 52.045,56.883 52.362,56.883 v1(52.403,56.924) ; v1(46.845,62.284) 46.926,62.284 46.984,62.341 49.55,62.341 49.912,61.979 50.626,61.979 51.343,61.261 U1.9 ; C21.1@49.784,59.921 50.622,59.921 51.156,60.455 51.899,60.455 U1.11 ; v1@52.505,57.041 U1.17 ; U1.7 52.905,62.753 54.282,64.129 54.282,64.179 54.382,64.279 54.417,64.279 54.481,64.344 54.641,64.344 v1(55.016,64.719) ; U1.24 55.305,57.31 v1@55.618,56.998 ; R33.2 55.448,35.799 55.448,36.637 55.565,36.754 60.427,36.754 ; v1(55.787,56.924) 55.806,56.905 56.524,56.905 56.624,57.005 C3.1 ; U1.31 56.617,60.861 v1(56.693,60.937) ; R34.1 60.391,36.718 60.427,36.754 ; 62.5,36.754 60.427,36.754
  Top Layer w0.3: 51.41,60.86 U1.10 U1.10
  Top Layer w0.4: U4.7 64.493,22.356 ; U4.10 64.38,23.856 64.493,23.742 64.497,23.739 ; R28.2@65.042,15.081 R28.2
  Top Layer w0.5: C20.1 48.759,61.177 49.704,61.177 50.021,60.86 51.41,60.86 ; v1(49.073,59.944) 49.756,59.944 49.759,59.947 C21.1@49.784,59.921 ; U8.5 59.692,33.102 60.205,33.615 60.6,33.615 C32.1
  Top Layer w0.56: R25.1 47.066,23.063 ; R22.1 R23.1 47.988,43.969 R24.1 ; R31.2 46.939,22.936 47.066,23.063 ; 51.232,23.114 51.181,23.063 47.066,23.063 ; 52.618,29.468 C22.2@52.618,29.693 ; U3.5 62.757,25.411 62.757,26.663 v1(62.763,26.67) v1(63.466,26.67) 64.169,26.67 64.497,26.342 64.497,23.739 ; 64.493,23.742 64.493,22.356 64.493,16.459 65.042,15.911 R28.2@65.042,15.081
  Top Layer w1: 46.736,61.369 47.252,61.369 C20.1@48.438,61.369 ; 47.988,43.256 R23.1@47.988,43.969 ; 51.41,31.496 52.451,31.496 ; 52.713,31.59 54.44,31.59 55.432,30.598 60.683,30.598 62.509,32.424 62.509,33.884 ; U3.8 58.917,30.429 ; C32.1 62.372,33.746 62.509,33.884 ; P2.11 64.12,39.398 62.509,37.787 62.509,33.884
  Top Layer w1.5: R9.2@51.598,46.101 51.598,47.229
  Bottom Layer w0.2: 46.845,58.877 48.235,58.877 ccw(c48.235,63.216) 51.304,60.149 54.41,63.255 ccw(c52.946,64.719) v1(55.016,64.719) ; v1(52.403,56.924) 52.405,56.926 56.339,56.926 56.693,57.28 v1(56.693,60.937)
  Bottom Layer w0.5: 46.845,59.921 49.05,59.921 v1(49.073,59.944)
  Bottom Layer w0.56: v1@58.67,26.721 v1(58.674,26.721) v1(59.182,26.721) v1@63.652,26.721
  Bottom Layer w1.5: v1(46.845,62.284) 46.845,59.921 46.845,58.877 46.845,54.45 48.026,53.269 48.012,53.255 48.012,33.979 50.521,31.471 52.299,31.471 ; 48.158,47.269 51.689,47.269
  other v1: 51.029,31.166 51.74,31.166 52.4,31.166 50.851,31.852 51.689,31.852 52.451,31.852 47.76,43.122 48.285,43.129 51.952,47.172 46.644,61.115 47.244,61.112 46.634,61.646 47.252,61.649
Wakeup: P2.2 U1.3 | length 11.8
  Top Layer w0.152: U1.3 54.533,61.888 54.533,62.263 54.967,62.697 64.811,62.697 65.25,62.258 P2.2
XIN: C27.2 U1.6 X1.3 | length 8.4
  Top Layer w0.152: U1.6 53.338,61.894 53.338,62.663 54.294,63.619 54.902,63.619 55.874,64.591 55.874,66.053 56.072,66.251 56.64,66.251 C27.2 56.7,66.246 57.805,66.246 58.328,66.77 X1.3
XOUT: C28.1 U1.5 X1.1 | length 9.2
  Top Layer w0.152: U1.5 53.715,61.871 53.715,62.609 54.42,63.314 55.029,63.314 56.179,64.465 56.179,65.18 56.303,65.305 56.673,65.305 C28.1 ; C28.1@56.743,65.324 56.974,65.556 59.272,65.556 60.128,64.7 X1.1
pads on no net: U2.12 U4.6 U6.3 USB1. USB1.A5 USB1.A8 USB1.B5 USB1.B8

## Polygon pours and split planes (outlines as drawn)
GND on Top Layer "NONET_L02_P-001" (solid, pour order 2): 41.148,71.291 67.183,71.291 67.183,8.382 41.148,8.382
no net on Top Layer "NONET_L02_P-001" (solid, pour order 0): 41.123,71.476
GND on Bottom Layer "NONET_L02_P-001" (solid, pour order 1): 41.148,71.29 67.183,71.29 67.183,8.382 41.148,8.382

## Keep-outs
Keep-Out Layer:
  lines w0.15: 41.148,8.382 67.148,8.382 67.148,78.382 41.148,78.382 41.148,8.382

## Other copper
Top Layer:
  region net VCC_33: 50.648,19.863 50.648,23.546 50.394,23.8 50.394,32.182 52.908,32.182 52.908,24.33 52.124,23.546 52.124,19.841
  region net 5V: 52.076,14.311 52.076,17.481 52.843,18.244 53.615,18.244 53.615,19.028 55.118,20.54 55.118,22.504 54.432,23.19 52.375,23.19 52.375,19.296 51.382,19.296 51.382,15.9 51.537,15.799 51.537,14.326
  pour cut-out: 51.765,66.627 51.765,64.443 51.791,64.417 52.807,64.417 52.807,66.627 52.781,66.652 51.994,66.652
  pour cut-out: 51.816,67.11
  pour cut-out: 51.816,67.11
  pour cut-out: 52.222,61.572 52.271,61.524 55.568,61.524 55.568,58.124 55.32,57.876 54.998,58.199 52.243,58.199
Bottom Layer:
  region net GND: 48.997,45.977

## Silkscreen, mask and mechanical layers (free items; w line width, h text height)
Top Overlay:
  drawing of 1179 lines, arcs and shapes, not listed
  text "DFT_MODE" at 44.374,65.049 h1.2
  text "RESET" at 63.729,63.551 h1.2 r90
  text "Wakeup" at 59.944,62.078 h1.2
  text "PA0/BOOT" at 45.187,60.147 h1 r90
  text "PB19/TX0" at 59.157,59.309 h1.2
  text "PA1" at 44.437,58.892 h1.2
  text "PA4" at 44.439,56.814 h1.2
  text "PB20/RX0" at 59.03,56.642 h1.2
  text "ES8311" at 55.372,54.407 h1.2
  text "PA7" at 44.415,54.248 h1.2
  text "PB11" at 61.57,54.229 h1.2
  text "PB10" at 61.62,51.562 h1.2
  text "PB0" at 45.114,51.537 h1.2 r90
  text "PB9" at 61.951,49.428 h1.2
  text "PB1" at 45.114,48.971 h1.2 r90
  text "PB8" at 62.027,46.711 h1.2
  text "PB2" at 45.114,46.406 h1.2 r90
  text "PB7" at 62.128,44.094 h1.2
  text "PB3" at 45.114,43.856 h1.2 r90
  text "PB6" at 62.179,41.504 h1.2
  text "PB4" at 45.11,40.945 h1.2 r90
  text "MIC-" at 46.572,40.958 h1.5
  text "MIC+" at 49.453,40.927 h1.5
  text "3.3V" at 62.179,38.913 h1.2
  text "PB5" at 45.085,38.303 h1.2 r90
  text "GND" at 61.95,36.54 h1.2
  text "GND" at 44.933,35.712 h1.2 r90
  text "SPK+" at 47.65,32.41 h1.5
  text "SPK-" at 47.574,28.016 h1.5
  text "CHT8305C" at 55.423,26.683 h1.2
  text "POWER" at 42.545,19.228 h1.2
  text "REST" at 62.255,8.915 h1.2
  text "BOOT" at 43.536,8.865 h1.2
Bottom Overlay:
  text "HLK-W800-KIT-V1.0" at 59.39,68.759 h1.5
  text "RESET" at 63.779,64.567 h1.2
  text "DFT_MODE" at 49.606,64.541 h1.2
  text "PA0/BOOT" at 49.327,61.951 h1.2
  text "Wakeup" at 63.805,61.951 h1.2
  text "PB19/TX0" at 63.754,59.36 h1.2
  text "PA1" at 45.872,59.309 h1.2
  text "PA4" at 45.898,56.871 h1.2
  text "PB20/RX0" at 63.779,56.744 h1.2
  text "PA7" at 45.822,54.254 h1.2
  text "PB11" at 63.652,54.102 h1.2
  text "PB0" at 45.949,51.714 h1.2
  text "PB10" at 63.652,51.714 h1.2
  text "PB1" at 45.949,49.149 h1.2
  text "PB9" at 63.703,48.92 h1.2
  text "PB2" at 45.898,46.66 h1.2
  text "PB8" at 63.703,46.504 h1.2
  text "PB7" at 63.668,44.127 h1.2
  text "PB3" at 45.999,44.044 h1.2
  text "PB4" at 45.999,41.605 h1.2
  text "PB6" at 63.678,41.554 h1.2
  text "3.3V" at 63.856,39.141 h1.2
  text "PB5" at 46.152,38.887 h1.2
  text "GND" at 46.431,36.449 h1.2
  text "GND" at 63.906,36.398 h1.2
Top Solder:
  region: 57.416,34.282 57.18,34.046 57.18,31.881 58.698,31.881 58.698,34.282

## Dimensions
65.608,64.798 to 65.608,36.858 on Top Overlay
42.748,36.858 to 65.608,36.858 on Top Overlay
42.748,36.858 to 42.748,39.398 on Top Overlay
41.148,78.382 to 41.148,8.382 on Top Overlay
41.148,78.382 to 67.148,78.382 on Top Overlay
